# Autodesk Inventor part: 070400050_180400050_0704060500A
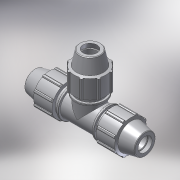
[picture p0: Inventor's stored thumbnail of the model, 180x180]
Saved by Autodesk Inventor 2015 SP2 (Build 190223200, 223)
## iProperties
Created: 2017-02
Part Number: 070400050_180400050_0704060500A
Material: PVC-Piping
Description: PLASSON TEE 50-50-50
Document SubType Name: Modeling
Designer: KIM
Mass: 92.6774 g
Surface Area: 199.44 cm^2
Volume: 66.1981 cm^3
Density: 1.4 g/cm^3
Appearance: Smooth - White
Author: KIM
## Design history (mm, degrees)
derived "07040.ipt"
feature "Solid1::07040.ipt"
tag "TaggingFeature1"
body "Solid1"
other parameters: "d4" = 10.5, "d5" = 31.5, "d7" = 96, "d11" = 4.2, "d13" = 120 deg, "d15" = 12 deg, "d16" = 83.52, "d18" = 2.5, "d19" = 35 deg, "d20" = 17.5 deg, "d21" = 89.28, "d23" = 0, "d25" = 360 deg, "d27" = 1.92, "d33" = 1, "d42" = 44.1, "d43" = 2.88, "d46" = 1.5, "d63" = 95, "d67" = 72, "d77" = 96, "d78" = 12 deg, "d79" = 126, "d80" = 120 deg, "d82" = 10.5, "d85" = 72, "d86" = 83.52, "d87" = 4.2, "d88" = 4.2, "d89" = 31.5, "d90" = 44.1, "d96" = 12.6, "d98" = 89.28, "d99" = 35 deg, "d100" = 17.5 deg, "d102" = 0, "d103" = 1.92, "d107" = 360 deg, "d109" = 1.5, "d112" = 2.5, "d118" = 360 deg, "d121" = 0, "d128" = 252, "d131" = 45, "d132" = 45, "d133" = 95, "d134" = 1.9, "d135" = 12.6, "d152" = 0, "d154" = 0, "d156" = 0, "d158" = 0, "E_" = 96, "A_" = 126, "l_" = 95, "H_" = 252
